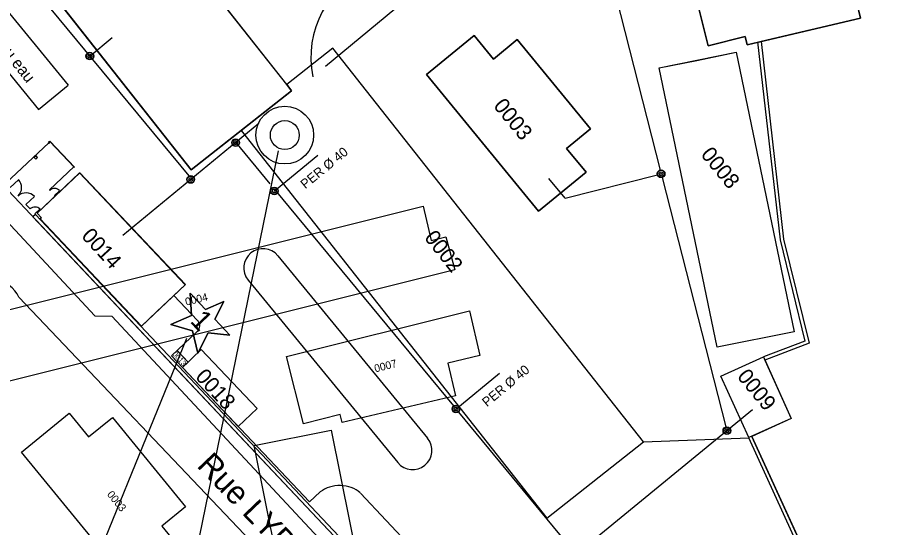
# Model space of a CAD drawing. Extents: x 703432 to 707394, y 7057985 to 7059523.
# Drawn here: x 704771.8 to 704884.5, y 7059261.6 to 7059327.9 of the extents above; entities that cross this region are included whole.
import ezdxf

# ---------------------------------------------------------------- set-up
doc = ezdxf.new("R2010")
doc.units = 0
for name, color, linetype in [('DH_HACHURE-MOTIF', 7, 'Continuous'), ('DH_TEXTE', 7, 'Continuous'), ('GEOSID_BATI_AERIEN _POLYGONE', 7, 'Continuous'), ('GEOSID_BATI_AERIEN_NUMERO', 7, 'Continuous'), ('GO_MUR_EXTERIEUR', 7, 'Continuous'), ('IMM_LIMITE PHYSIQUE', 7, 'Continuous'), ('LIB_08', 7, 'Continuous'), ('RES_BASSE TENSION AERIEN', 7, 'Continuous'), ('RES_CHAUFFAGE SECONDAIRE', 7, 'Continuous'), ('RES_EAU BASSE PRESSION', 7, 'Continuous'), ('RES_EAU BASSE PRESSION - EQUIP - TEXTE', 7, 'Continuous'), ('SID_NUMERO_BATI', 7, 'Continuous'), ('SID_POLYLIGNES_BATI', 7, 'Continuous'), ('SID_POLYLIGNES_IMMEUBLE', 7, 'Continuous'), ('VOIRIE_BORDURE', 7, 'Continuous'), ('VOIRIE_ROUTE', 7, 'Continuous')]:
    doc.layers.add(name, color=color, linetype=linetype)

msp = doc.modelspace()

# ---------------------------------------------------------------- linework, layer by layer
at = {"layer": 'DH_HACHURE-MOTIF'}
for p, q in [((704855.21, 7059321.36), (704860.12, 7059322.32)), ((704862.75, 7059285.03), (704855.21, 7059321.36)), ((704872.77, 7059287.04), (704862.75, 7059285.03)), ((704863.24, 7059281.27), (704868.77, 7059283.77)), ((704866.85, 7059273.28), (704863.24, 7059281.27)), ((704872.38, 7059275.78), (704866.85, 7059273.28))]:
    msp.add_line(p, q, dxfattribs=at)
for points in [[(704764.01, 7059346.61), (704766.21, 7059343.82), (704794.39, 7059308.1), (704800.87, 7059313.21), (704807.43, 7059318.38), (704806.81, 7059319.17), (704777.07, 7059356.86), (704776.77, 7059357.24), (704763.73, 7059346.96), (704764.01, 7059346.61)], [(704866.39, 7059325.41), (704866.63, 7059324.35), (704881.38, 7059327.83), (704880.38, 7059332.05), (704884.52, 7059333.08), (704883.19, 7059338.88), (704882.76, 7059338.77), (704859.41, 7059332.93), (704861.6, 7059324.2), (704866.39, 7059325.41)], [(704833.68, 7059322.48), (704831.15, 7059325.58), (704824.96, 7059320.51), (704839.54, 7059302.72), (704845.73, 7059307.79), (704843.19, 7059310.88), (704846.28, 7059313.42), (704836.78, 7059325.02), (704833.68, 7059322.48)], [(704853.19, 7059272.73), (704812.81, 7059323.9), (704806.81, 7059319.17), (704807.43, 7059318.38), (704800.87, 7059313.21), (704840.63, 7059262.82), (704853.19, 7059272.73)], [(704860.12, 7059322.32), (704865.23, 7059323.38), (704872.77, 7059287.04)], [(704792.63, 7059284.53), (704792.56, 7059284.6), (704791.84, 7059283.91), (704793.26, 7059282.41), (704793.98, 7059283.1), (704792.63, 7059284.53)], [(704868.77, 7059283.77), (704868.86, 7059283.57), (704872.38, 7059275.78)]]:
    msp.add_lwpolyline(points, dxfattribs=at)
for points in [[(704789.88, 7059289.63), (704793.6, 7059293.14), (704779.88, 7059307.69), (704774.36, 7059302.48), (704774.94, 7059301.87), (704774.78, 7059301.71), (704787.92, 7059287.78)], [(704795.71, 7059284.72), (704793.26, 7059282.41), (704800.5, 7059274.73), (704802.95, 7059277.05)]]:
    msp.add_lwpolyline(points, close=True, dxfattribs=at)
at = {"layer": 'GEOSID_BATI_AERIEN _POLYGONE'}
for points in [[(704764.38, 7059288.32), (704824.53, 7059303.35), (704825.56, 7059298.9), (704827.5, 7059299.38), (704828.65, 7059295.1), (704766.56, 7059279.59)], [(704806.78, 7059283.82), (704830.56, 7059289.76), (704831.89, 7059283.97), (704827.75, 7059282.94), (704828.75, 7059278.72), (704814, 7059275.23), (704813.76, 7059276.3), (704808.97, 7059275.09)], [(704772.33, 7059271.39), (704778.52, 7059276.46), (704781.05, 7059273.37), (704784.15, 7059275.9), (704793.66, 7059264.3), (704790.56, 7059261.77), (704793.1, 7059258.67), (704786.91, 7059253.6)], [(704802.58, 7059272.25), (704812.6, 7059274.26), (704819.92, 7059237.89), (704809.91, 7059235.87)]]:
    msp.add_lwpolyline(points, close=True, dxfattribs=at)
at = {"layer": 'GO_MUR_EXTERIEUR'}
for p, q in [((704776.77, 7059357.24), (704807.43, 7059318.38)), ((704794.39, 7059308.1), (704763.73, 7059346.96)), ((704861.6, 7059324.2), (704859.41, 7059332.93)), ((704880.38, 7059332.05), (704881.38, 7059327.83)), ((704824.96, 7059320.51), (704831.15, 7059325.58)), ((704831.15, 7059325.58), (704833.68, 7059322.48)), ((704833.68, 7059322.48), (704836.78, 7059325.02)), ((704836.78, 7059325.02), (704846.28, 7059313.42)), ((704812.81, 7059323.9), (704806.81, 7059319.17)), ((704853.19, 7059272.73), (704812.81, 7059323.9)), ((704855.21, 7059321.36), (704865.23, 7059323.38)), ((704865.23, 7059323.38), (704872.77, 7059287.04)), ((704839.54, 7059302.72), (704824.96, 7059320.51)), ((704862.75, 7059285.03), (704855.21, 7059321.36)), ((704807.43, 7059318.38), (704794.39, 7059308.1)), ((704807.43, 7059318.38), (704800.87, 7059313.21)), ((704806.81, 7059319.17), (704807.43, 7059318.38)), ((704800.87, 7059313.21), (704840.63, 7059262.82)), ((704846.28, 7059313.42), (704843.19, 7059310.88)), ((704843.19, 7059310.88), (704845.73, 7059307.79)), ((704779.91, 7059307.72), (704774.36, 7059302.48)), ((704793.64, 7059293.18), (704779.91, 7059307.72)), ((704845.73, 7059307.79), (704839.54, 7059302.72)), ((704787.92, 7059287.78), (704793.64, 7059293.18)), ((704872.77, 7059287.04), (704862.75, 7059285.03)), ((704791.84, 7059283.91), (704792.56, 7059284.6)), ((704792.56, 7059284.6), (704793.98, 7059283.1)), ((704793.26, 7059282.41), (704791.84, 7059283.91)), ((704863.24, 7059281.27), (704868.77, 7059283.77)), ((704868.77, 7059283.77), (704872.38, 7059275.78)), ((704793.98, 7059283.1), (704793.26, 7059282.41)), ((704866.85, 7059273.28), (704863.24, 7059281.27)), ((704872.38, 7059275.78), (704866.85, 7059273.28)), ((704840.63, 7059262.82), (704853.19, 7059272.73))]:
    msp.add_line(p, q, dxfattribs=at)
for points in [[(704881.38, 7059327.83), (704866.63, 7059324.35), (704866.39, 7059325.41), (704861.6, 7059324.2)], [(704774.36, 7059302.48), (704774.94, 7059301.87), (704774.78, 7059301.71), (704787.92, 7059287.78)]]:
    msp.add_lwpolyline(points, dxfattribs=at)
msp.add_lwpolyline([(704795.71, 7059284.72), (704802.95, 7059277.05), (704800.5, 7059274.73), (704793.26, 7059282.41)], close=True, dxfattribs=at)
at = {"layer": 'IMM_LIMITE PHYSIQUE'}
for p, q in [((704770.31, 7059306.37), (704775.87, 7059311.62)), ((704775.96, 7059305.48), (704779.17, 7059308.51)), ((704770.86, 7059305.79), (704771.95, 7059306.81)), ((704772.92, 7059303.6), (704774.01, 7059304.63)), ((704775.96, 7059305.48), (704776.02, 7059305.42)), ((704777.29, 7059305.38), (704776.63, 7059304.77)), ((704776.63, 7059304.77), (704776.69, 7059304.7)), ((704772.92, 7059303.6), (704773.47, 7059303.02)), ((704774.74, 7059302.98), (704774.09, 7059302.36)), ((704774.09, 7059302.36), (704774.15, 7059302.3)), ((704774.15, 7059302.3), (704773.82, 7059301.99)), ((704773.82, 7059301.99), (704837.52, 7059234.47)), ((704774.15, 7059302.3), (704837.75, 7059234.88))]:
    msp.add_line(p, q, dxfattribs=at)
for points in [[(704868.01, 7059324.73), (704870.94, 7059299.01), (704874.16, 7059285.83), (704868.78, 7059283.77)], [(704868.46, 7059324.78), (704871.38, 7059299.08), (704874.69, 7059285.55), (704868.94, 7059283.35)], [(704875.79, 7059248.63), (704874.76, 7059255.98), (704866.86, 7059273.26)], [(704876.24, 7059248.69), (704875.2, 7059256.1), (704867.27, 7059273.44)]]:
    msp.add_lwpolyline(points, dxfattribs=at)
for points in [[(704776.03, 7059311.77), (704775.79, 7059311.71), (704775.95, 7059311.53)], [(704776.03, 7059311.77), (704779.19, 7059308.42), (704779.23, 7059308.45), (704776.07, 7059311.8)], [(704773.99, 7059309.7), (704774.2, 7059309.49), (704774.44, 7059309.71), (704774.24, 7059309.93)]]:
    msp.add_lwpolyline(points, close=True, dxfattribs=at)
for centre, radius, start, end in [((704770.86, 7059305.79), 1.5, 313.3307, 43.3307), ((704772.92, 7059303.6), 1.5, 43.3307, 133.3307), ((704776.63, 7059304.77), 0.9, 43.3307, 133.3307), ((704774.09, 7059302.36), 0.9, 43.3307, 133.3307)]:
    msp.add_arc(centre, radius, start, end, dxfattribs=at)
at = {"layer": 'LIB_08'}
for p, q in [((704796.25, 7059289.95), (704794.28, 7059292.04)), ((704794.28, 7059292.04), (704794.45, 7059289.17)), ((704798.62, 7059290.97), (704796.25, 7059289.95)), ((704797.46, 7059288.67), (704798.62, 7059290.97)), ((704794.45, 7059289.17), (704791.73, 7059288)), ((704799.43, 7059286.58), (704797.46, 7059288.67)), ((704795.25, 7059284.27), (704796.58, 7059286.92)), ((704796.58, 7059286.92), (704799.43, 7059286.58))]:
    msp.add_line(p, q, dxfattribs=at)
for points in [[(704818.61, 7059229.1), (704794.32, 7059254.63), (704805.74, 7059310.57)], [(704791.73, 7059288), (704794.57, 7059287.15), (704794.57, 7059287.15)], [(704794.57, 7059287.15), (704794.57, 7059287.15), (704795.25, 7059284.27)], [(704797.43, 7059226.8), (704778.01, 7059247.38), (704793.84, 7059286.23)]]:
    msp.add_lwpolyline(points, dxfattribs=at)
msp.add_lwpolyline([(704794.28, 7059292.04), (704796.25, 7059289.95), (704798.62, 7059290.97), (704797.46, 7059288.67), (704799.43, 7059286.58), (704796.58, 7059286.92), (704795.25, 7059284.27), (704794.57, 7059287.15), (704791.73, 7059288), (704794.45, 7059289.17)], close=True, dxfattribs=at)
for radius in [3.75, 1.88, 1.88]:
    msp.add_circle((704806.56, 7059312.61), radius, dxfattribs=at)
at = {"layer": 'RES_BASSE TENSION AERIEN'}
msp.add_line((704853.19, 7059272.73), (704866.86, 7059273.26), dxfattribs=at)
at = {"layer": 'RES_CHAUFFAGE SECONDAIRE'}
msp.add_arc((704822.5, 7059322.74), 12.55, 112.1042, 191.7308, dxfattribs=at)
at = {"layer": 'RES_EAU BASSE PRESSION'}
for p, q in [((704762.6, 7059345.41), (704794.07, 7059307.33)), ((704848.21, 7059336.01), (704855.35, 7059308.06)), ((704811.85, 7059321.58), (704820.86, 7059329.03)), ((704781.22, 7059322.88), (704784.14, 7059325.29)), ((704803.17, 7059314.13), (704785.52, 7059299.55)), ((704800.13, 7059311.69), (704804.61, 7059306.27)), ((704805.2, 7059305.35), (704810.87, 7059310)), ((704843, 7059304.39), (704840.89, 7059306.97)), ((704843, 7059304.39), (704854.99, 7059307.45)), ((704855.6, 7059307.09), (704863.88, 7059274.66)), ((704805.25, 7059305.49), (704828.47, 7059277.39)), ((704828.8, 7059276.99), (704834.45, 7059281.66)), ((704829.13, 7059276.6), (704844.03, 7059258.56)), ((704867.34, 7059276.91), (704844.48, 7059258.18))]:
    msp.add_line(p, q, dxfattribs=at)
at = {"layer": 'RES_EAU BASSE PRESSION - EQUIP - TEXTE'}
for centre, radius in [((704781.22, 7059322.88), 0.5), ((704781.22, 7059322.88), 0.45), ((704781.22, 7059322.88), 0.25), ((704781.22, 7059322.88), 0.05), ((704800.16, 7059311.64), 0.5), ((704800.16, 7059311.64), 0.45), ((704800.16, 7059311.64), 0.25), ((704800.16, 7059311.64), 0.05), ((704855.47, 7059307.58), 0.5), ((704855.47, 7059307.58), 0.45), ((704794.34, 7059306.84), 0.5), ((704794.34, 7059306.84), 0.45), ((704794.34, 7059306.84), 0.25), ((704794.34, 7059306.84), 0.05), ((704855.47, 7059307.58), 0.25), ((704855.47, 7059307.58), 0.05), ((704805.2, 7059305.35), 0.5), ((704805.2, 7059305.35), 0.45), ((704805.2, 7059305.35), 0.25), ((704805.2, 7059305.35), 0.05), ((704828.8, 7059276.99), 0.5), ((704828.8, 7059276.99), 0.45), ((704828.8, 7059276.99), 0.25), ((704828.8, 7059276.99), 0.05), ((704864.01, 7059274.18), 0.5), ((704864.01, 7059274.18), 0.45), ((704864.01, 7059274.18), 0.25), ((704864.01, 7059274.18), 0.05)]:
    msp.add_circle(centre, radius, dxfattribs=at)
at = {"layer": 'SID_POLYLIGNES_BATI'}
for p, q in [((704776.77, 7059357.24), (704807.43, 7059318.38)), ((704794.39, 7059308.1), (704763.73, 7059346.96)), ((704824.96, 7059320.51), (704831.15, 7059325.58)), ((704831.15, 7059325.58), (704833.68, 7059322.48)), ((704833.68, 7059322.48), (704836.78, 7059325.02)), ((704836.78, 7059325.02), (704846.28, 7059313.42)), ((704812.81, 7059323.9), (704806.81, 7059319.17)), ((704853.19, 7059272.73), (704812.81, 7059323.9)), ((704855.21, 7059321.36), (704865.23, 7059323.38)), ((704865.23, 7059323.38), (704872.77, 7059287.04)), ((704839.54, 7059302.72), (704824.96, 7059320.51)), ((704862.75, 7059285.03), (704855.21, 7059321.36)), ((704807.43, 7059318.38), (704794.39, 7059308.1)), ((704807.43, 7059318.38), (704800.87, 7059313.21)), ((704806.81, 7059319.17), (704807.43, 7059318.38)), ((704800.87, 7059313.21), (704840.63, 7059262.82)), ((704846.28, 7059313.42), (704843.19, 7059310.88)), ((704843.19, 7059310.88), (704845.73, 7059307.79)), ((704779.88, 7059307.69), (704774.36, 7059302.48)), ((704793.6, 7059293.14), (704779.88, 7059307.69)), ((704845.73, 7059307.79), (704839.54, 7059302.72)), ((704787.92, 7059287.78), (704793.6, 7059293.14)), ((704872.77, 7059287.04), (704862.75, 7059285.03)), ((704791.84, 7059283.91), (704792.56, 7059284.6)), ((704792.56, 7059284.6), (704793.98, 7059283.1)), ((704793.26, 7059282.41), (704791.84, 7059283.91)), ((704863.24, 7059281.27), (704868.77, 7059283.77)), ((704868.77, 7059283.77), (704872.38, 7059275.78)), ((704793.98, 7059283.1), (704793.26, 7059282.41)), ((704866.85, 7059273.28), (704863.24, 7059281.27)), ((704872.38, 7059275.78), (704866.85, 7059273.28)), ((704840.63, 7059262.82), (704853.19, 7059272.73))]:
    msp.add_line(p, q, dxfattribs=at)
msp.add_lwpolyline([(704774.36, 7059302.48), (704774.94, 7059301.87), (704774.78, 7059301.71), (704787.92, 7059287.78)], dxfattribs=at)
msp.add_lwpolyline([(704795.71, 7059284.72), (704802.95, 7059277.05), (704800.5, 7059274.73), (704793.26, 7059282.41)], close=True, dxfattribs=at)
at = {"layer": 'SID_POLYLIGNES_IMMEUBLE'}
for p, q in [((704880.38, 7059332.05), (704881.38, 7059327.83)), ((704837.52, 7059234.47), (704748.31, 7059329.03)), ((704881.38, 7059327.83), (704868.46, 7059324.78)), ((704874.69, 7059285.55), (704868.94, 7059283.35)), ((704868.94, 7059283.35), (704872.38, 7059275.78)), ((704872.38, 7059275.78), (704867.27, 7059273.44)), ((704867.27, 7059273.44), (704875.2, 7059256.1))]:
    msp.add_line(p, q, dxfattribs=at)
msp.add_lwpolyline([(704868.46, 7059324.78), (704871.38, 7059299.08), (704874.69, 7059285.55)], dxfattribs=at)
at = {"layer": 'VOIRIE_BORDURE'}
for p, q in [((704767.45, 7059332.5), (704778.41, 7059319.12)), ((704761.93, 7059331.35), (704774.55, 7059315.95)), ((704774.55, 7059315.95), (704778.41, 7059319.12)), ((704805.67, 7059296.93), (704825.12, 7059273.2)), ((704801.8, 7059293.76), (704821.25, 7059270.03)), ((704792.15, 7059291.77), (704795.23, 7059288.49)), ((704795.19, 7059287.08), (704791.84, 7059283.91)), ((704791.84, 7059283.91), (704809.77, 7059264.91)), ((704809.77, 7059264.91), (704811.16, 7059266.22)), ((704816.39, 7059266.07), (704826.66, 7059255.18))]:
    msp.add_line(p, q, dxfattribs=at)
for centre, radius, start, end in [((704803.73, 7059295.35), 2.5, 39.3307, 219.3307), ((704794.51, 7059287.81), 1, 313.3306, 43.3306), ((704823.18, 7059271.61), 2.5, 219.3307, 39.3307)]:
    msp.add_arc(centre, radius, start, end, dxfattribs=at)
msp.add_ellipse((704813.69, 7059264.04), major_axis=(-3.68, 0), ratio=0.816097, start_param=3.897855, end_param=5.468654, dxfattribs=at)
at = {"layer": 'VOIRIE_ROUTE'}
for p, q in [((704761.43, 7059311.05), (704781.89, 7059289.12)), ((704828.72, 7059231.87), (704772.01, 7059291.53)), ((704781.89, 7059289.12), (704784.13, 7059289.06)), ((704784.08, 7059289.06), (704836.4, 7059232.99))]:
    msp.add_line(p, q, dxfattribs=at)
msp.add_arc((704768.39, 7059289.82), 4, 25.2763, 139.6675, dxfattribs=at)

# ---------------------------------------------------------------- texts
at = {"layer": 'DH_TEXTE'}
msp.add_text('Rue LYDERIC', height=3, rotation=313.8024, dxfattribs=at).set_placement((704795.02, 7059269.55))
at = {"layer": 'GEOSID_BATI_AERIEN_NUMERO'}
for s, rotation, p in [('0004', 13.5243, (704793.74, 7059290.43)), ('0007', 14.5051, (704818.33, 7059281.75)), ('0003', 309.3307, (704783.39, 7059265.86))]:
    msp.add_text(s, height=1, rotation=rotation, dxfattribs=at).set_placement(p)
at = {"layer": 'LIB_08'}
msp.add_text('1', height=2.65, rotation=313.3307, dxfattribs=at).set_placement((704794.15, 7059288.35))
at = {"layer": 'RES_EAU BASSE PRESSION - EQUIP - TEXTE'}
for s, height, rotation, p in [('Vers réseau eau', 1.5, 308.2727, (704763.94, 7059330.84)), ('PER %%C 40', 1.219, 39.3307, (704809.22, 7059305.56)), ('PER %%C 40', 1.219, 39.5678, (704832.83, 7059277.22))]:
    msp.add_text(s, height=height, rotation=rotation, dxfattribs=at).set_placement(p)
at = {"layer": 'SID_NUMERO_BATI'}
for s, height, rotation, p in [('0003', 2, 309.3307, (704833.58, 7059316.37)), ('0008', 2, 309.3307, (704860.53, 7059310.05)), ('0014', 2, 312.5129, (704780.02, 7059299.41)), ('0002', 2, 308.2727, (704824.6, 7059299.25)), ('0013', 0.698, 312.5129, (704791.88, 7059284.1)), ('0018', 2, 312.5129, (704794.83, 7059281.12)), ('0009', 2, 309.3307, (704865.25, 7059281.19))]:
    msp.add_text(s, height=height, rotation=rotation, dxfattribs=at).set_placement(p)

doc.saveas('drawing.dxf')
